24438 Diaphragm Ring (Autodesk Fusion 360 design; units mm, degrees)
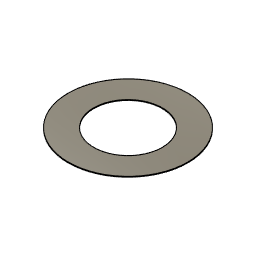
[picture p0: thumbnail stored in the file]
sketch "Main Profile" plane through (0, 0, 0) normal (0, 0, 1) x axis (1, 0, 0)
  circle C1 centre (0, 0) radius 42.8625
  circle C2 centre (0, 0) radius 24.6062
  point P1 (0, 0)
  point P2 (0, 0)
  point P3 (0, 0)
  coincident P1 P2
  coincident P1 P3
  dimension "d1" diameter C1 = 85.725 (= "3 3/8")
  dimension "d2" diameter C2 = 49.2125
extrude "Extrude1" new body sketch "Main Profile" along normal blind 0.508 bodies "24438 Diaphragm Ring"
named bodies: "24438 Diaphragm Ring"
